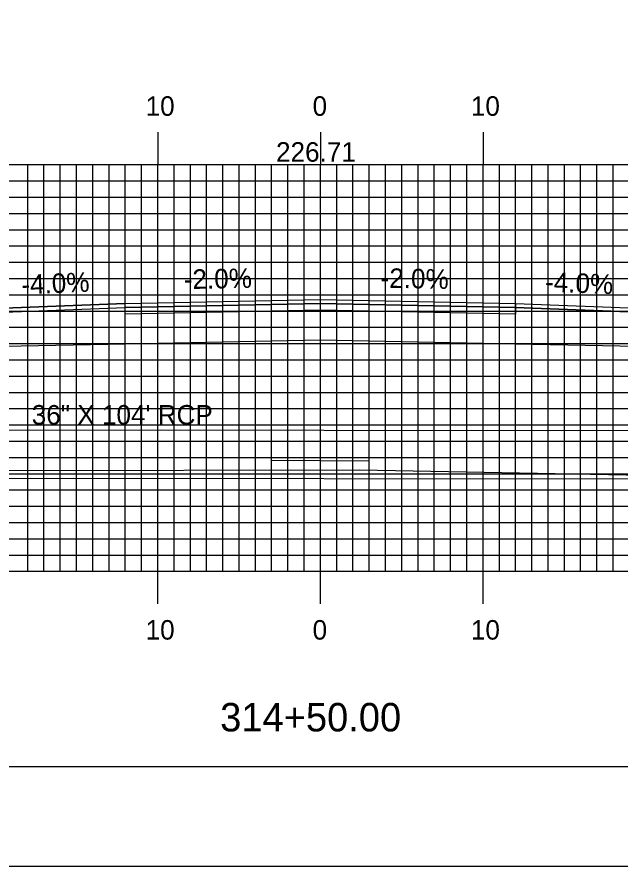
# Model space of a CAD drawing. Extents: x 1819244 to 1819587, y 442591 to 442811.
# Drawn here: x 1819391 to 1819428.1, y 442590.5 to 442642.7 of the extents above; entities that cross this region are included whole.
import ezdxf

# ---------------------------------------------------------------- set-up
doc = ezdxf.new("R2010")
doc.units = 0
for name, color, linetype in [('ANNOTATION', 7, 'Continuous'), ('BORDER', 7, 'Continuous'), ('D_Drainage_Culvert', 7, 'Continuous'), ('D_Drainage_Text', 7, 'Continuous'), ('D_Roadway_Centerline', 7, 'Continuous'), ('D_Roadway_Centerline_Text', 7, 'Continuous'), ('D_Roadway_Edge_Shoulder', 7, 'Continuous'), ('D_Roadway_Edge_TW', 7, 'Continuous'), ('D_Roadway_Pavement', 7, 'Continuous'), ('D_Roadway_SubGrade', 7, 'Continuous'), ('H_V ANNOTATION', 7, 'Continuous'), ('MAJOR', 7, 'Continuous'), ('MINOR', 7, 'Continuous'), ('PLOT BOUNDARY', 7, 'Continuous'), ('S_Roadway_Centerline', 7, 'Continuous')]:
    doc.layers.add(name, color=color, linetype=linetype)

msp = doc.modelspace()

# ---------------------------------------------------------------- linework, layer by layer
at = {"layer": 'BORDER'}
msp.add_lwpolyline([(1819260.065, 442596.665), (1819580.065, 442596.665), (1819580.065, 442806.665), (1819260.065, 442806.665)], close=True, dxfattribs=at)
at = {"layer": 'D_Drainage_Culvert'}
msp.add_line((1819406.665, 442615.492), (1819412.665, 442615.45), dxfattribs=at)
msp.add_lwpolyline([(1819357.867, 442614.363), (1819357.868, 442617.363), (1819461.868, 442617.321), (1819461.867, 442614.321)], close=True, dxfattribs=at)
at = {"layer": 'D_Roadway_Centerline'}
msp.add_lwpolyline([(1819366.978, 442618.255), (1819377.665, 442621.817), (1819379.491, 442622.273), (1819389.665, 442624.817), (1819397.665, 442625.137), (1819409.665, 442625.377), (1819421.665, 442625.137), (1819429.665, 442624.817), (1819439.839, 442622.273), (1819441.665, 442621.817), (1819452.46, 442618.218)], dxfattribs=at)
at = {"layer": 'D_Roadway_Edge_Shoulder'}
for points in [[(1819397.665, 442625.137), (1819389.665, 442624.817), (1819389.665, 442624.567), (1819397.665, 442624.887)], [(1819421.665, 442625.137), (1819429.665, 442624.817), (1819429.665, 442624.567), (1819421.665, 442624.887)]]:
    msp.add_lwpolyline(points, close=True, dxfattribs=at)
at = {"layer": 'D_Roadway_Edge_TW'}
msp.add_lwpolyline([(1819397.665, 442624.887), (1819397.665, 442625.137), (1819409.665, 442625.377), (1819421.665, 442625.137), (1819421.665, 442624.887), (1819409.665, 442625.127)], close=True, dxfattribs=at)
at = {"layer": 'D_Roadway_Pavement'}
msp.add_lwpolyline([(1819397.665, 442624.47), (1819397.665, 442624.887), (1819409.665, 442625.127), (1819421.665, 442624.887), (1819421.665, 442624.47), (1819409.665, 442624.71)], close=True, dxfattribs=at)
at = {"layer": 'D_Roadway_SubGrade'}
msp.add_lwpolyline([(1819397.665, 442622.637), (1819379.491, 442622.273), (1819389.665, 442624.817), (1819389.665, 442624.567), (1819397.665, 442624.887), (1819409.665, 442625.127), (1819421.665, 442624.887), (1819429.665, 442624.567), (1819429.665, 442624.817), (1819439.839, 442622.273), (1819421.665, 442622.637), (1819409.665, 442622.877)], close=True, dxfattribs=at)
at = {"layer": 'MAJOR'}
for p, q in [((1819399.665, 442635.669), (1819399.665, 442633.665)), ((1819409.665, 442635.669), (1819409.665, 442633.665)), ((1819419.665, 442635.669), (1819419.665, 442633.665)), ((1819269.665, 442633.665), (1819549.665, 442633.665)), ((1819269.665, 442633.665), (1819549.665, 442633.665)), ((1819399.665, 442608.665), (1819399.665, 442633.665)), ((1819409.665, 442608.665), (1819409.665, 442633.665)), ((1819419.665, 442608.665), (1819419.665, 442633.665)), ((1819269.665, 442628.665), (1819549.665, 442628.665)), ((1819269.665, 442623.665), (1819549.665, 442623.665)), ((1819269.665, 442618.665), (1819549.665, 442618.665)), ((1819269.665, 442613.665), (1819549.665, 442613.665)), ((1819269.665, 442608.665), (1819549.665, 442608.665)), ((1819269.665, 442608.665), (1819549.665, 442608.665)), ((1819399.665, 442606.661), (1819399.665, 442608.665)), ((1819409.665, 442606.661), (1819409.665, 442608.665)), ((1819419.665, 442606.661), (1819419.665, 442608.665))]:
    msp.add_line(p, q, dxfattribs=at)
at = {"layer": 'MINOR'}
for p, q in [((1819391.665, 442608.665), (1819391.665, 442633.665)), ((1819392.665, 442608.665), (1819392.665, 442633.665)), ((1819393.665, 442608.665), (1819393.665, 442633.665)), ((1819394.665, 442608.665), (1819394.665, 442633.665)), ((1819395.665, 442608.665), (1819395.665, 442633.665)), ((1819396.665, 442608.665), (1819396.665, 442633.665)), ((1819397.665, 442608.665), (1819397.665, 442633.665)), ((1819398.665, 442608.665), (1819398.665, 442633.665)), ((1819400.665, 442608.665), (1819400.665, 442633.665)), ((1819401.665, 442608.665), (1819401.665, 442633.665)), ((1819402.665, 442608.665), (1819402.665, 442633.665)), ((1819403.665, 442608.665), (1819403.665, 442633.665)), ((1819404.665, 442608.665), (1819404.665, 442633.665)), ((1819405.665, 442608.665), (1819405.665, 442633.665)), ((1819406.665, 442608.665), (1819406.665, 442633.665)), ((1819407.665, 442608.665), (1819407.665, 442633.665)), ((1819408.665, 442608.665), (1819408.665, 442633.665)), ((1819410.665, 442608.665), (1819410.665, 442633.665)), ((1819411.665, 442608.665), (1819411.665, 442633.665)), ((1819412.665, 442608.665), (1819412.665, 442633.665)), ((1819413.665, 442608.665), (1819413.665, 442633.665)), ((1819414.665, 442608.665), (1819414.665, 442633.665)), ((1819415.665, 442608.665), (1819415.665, 442633.665)), ((1819416.665, 442608.665), (1819416.665, 442633.665)), ((1819417.665, 442608.665), (1819417.665, 442633.665)), ((1819418.665, 442608.665), (1819418.665, 442633.665)), ((1819420.665, 442608.665), (1819420.665, 442633.665)), ((1819421.665, 442608.665), (1819421.665, 442633.665)), ((1819422.665, 442608.665), (1819422.665, 442633.665)), ((1819423.665, 442608.665), (1819423.665, 442633.665)), ((1819424.665, 442608.665), (1819424.665, 442633.665)), ((1819425.665, 442608.665), (1819425.665, 442633.665)), ((1819426.665, 442608.665), (1819426.665, 442633.665)), ((1819427.665, 442608.665), (1819427.665, 442633.665)), ((1819269.665, 442632.665), (1819549.665, 442632.665)), ((1819269.665, 442631.665), (1819549.665, 442631.665)), ((1819269.665, 442630.665), (1819549.665, 442630.665)), ((1819269.665, 442629.665), (1819549.665, 442629.665)), ((1819269.665, 442627.665), (1819549.665, 442627.665)), ((1819269.665, 442626.665), (1819549.665, 442626.665)), ((1819269.665, 442625.665), (1819549.665, 442625.665)), ((1819269.665, 442624.665), (1819549.665, 442624.665)), ((1819269.665, 442622.665), (1819549.665, 442622.665)), ((1819269.665, 442621.665), (1819549.665, 442621.665)), ((1819269.665, 442620.665), (1819549.665, 442620.665)), ((1819269.665, 442619.665), (1819549.665, 442619.665)), ((1819269.665, 442617.665), (1819549.665, 442617.665)), ((1819269.665, 442616.665), (1819549.665, 442616.665)), ((1819269.665, 442615.665), (1819549.665, 442615.665)), ((1819269.665, 442614.665), (1819549.665, 442614.665)), ((1819269.665, 442612.665), (1819549.665, 442612.665)), ((1819269.665, 442611.665), (1819549.665, 442611.665)), ((1819269.665, 442610.665), (1819549.665, 442610.665)), ((1819269.665, 442609.665), (1819549.665, 442609.665))]:
    msp.add_line(p, q, dxfattribs=at)
at = {"layer": 'PLOT BOUNDARY'}
msp.add_lwpolyline([(1819243.878, 442590.547), (1819583.878, 442590.547), (1819583.878, 442810.547), (1819243.878, 442810.547)], close=True, dxfattribs=at)
at = {"layer": 'S_Roadway_Centerline'}
msp.add_lwpolyline([(1819269.665, 442615.62), (1819293.864, 442614.517), (1819306.637, 442614.196), (1819311.939, 442614.111), (1819327.13, 442614.269), (1819335.506, 442614.454), (1819347.417, 442614.452), (1819360.584, 442614.34), (1819366.063, 442614.563), (1819375.686, 442614.381), (1819387.593, 442614.823), (1819390.429, 442614.853), (1819412.092, 442614.909), (1819428.463, 442614.6), (1819437.115, 442614.23), (1819454.085, 442614.332), (1819455.159, 442614.334), (1819459.077, 442614.335), (1819469.488, 442614.315), (1819471.654, 442614.398)], dxfattribs=at)

# ---------------------------------------------------------------- texts
at = {"layer": 'ANNOTATION'}
for s, rotation, p in [('-4.0%', 2.2906, (1819391.296, 442625.684)), ('-2.0%', 1.1458, (1819401.271, 442626.009)), ('-2.0%', 358.8542, (1819413.351, 442626.103)), ('-4.0%', 357.7094, (1819423.456, 442625.867))]:
    msp.add_text(s, height=1.2, rotation=rotation, dxfattribs=at).set_placement(p)
at = {"layer": 'D_Drainage_Text'}
msp.add_text('36" X 104\' RCP', height=1.2, dxfattribs=at).set_placement((1819391.913, 442617.684))
at = {"layer": 'D_Roadway_Centerline'}
for s, p in [('C', (1819409.659, 442625.377)), ('L', (1819409.665, 442625.369))]:
    msp.add_text(s, height=0.0146, dxfattribs=at).set_placement(p)
at = {"layer": 'D_Roadway_Centerline_Text'}
msp.add_text('226.71', height=1.2, dxfattribs=at).set_placement((1819406.935, 442633.844))
at = {"layer": 'H_V ANNOTATION'}
for s, height, p in [('10', 1.2, (1819398.915, 442636.665)), ('0', 1.2, (1819409.183, 442636.665)), ('10', 1.2, (1819418.915, 442636.665)), ('10', 1.2, (1819398.915, 442604.465)), ('0', 1.2, (1819409.183, 442604.465)), ('10', 1.2, (1819418.915, 442604.465)), ('314+50.00', 1.75, (1819403.5, 442598.821))]:
    msp.add_text(s, height=height, dxfattribs=at).set_placement(p)

doc.saveas('drawing.dxf')
